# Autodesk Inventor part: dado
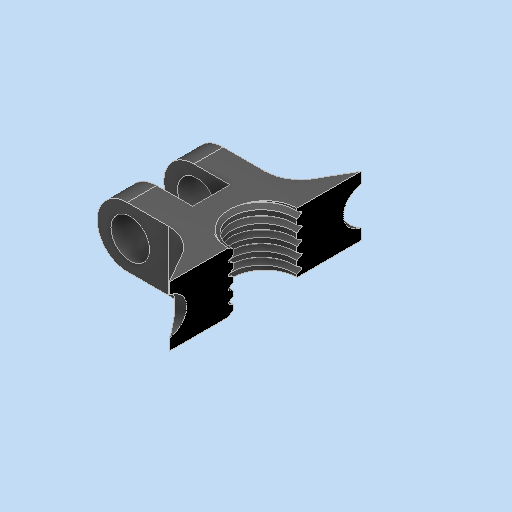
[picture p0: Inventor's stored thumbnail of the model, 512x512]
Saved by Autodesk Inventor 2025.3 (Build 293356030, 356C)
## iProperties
Created: 2026-05
Part Number: dado
Material: Generico
Document SubType Name: Modeling
Designer: R5800u
Density: 1 g/cm^3
Appearance: Default
Mass: 0.53278 g
Surface Area: 9.06232 cm^2
Volume: 0.53278 cm^3
Sending System: Autodesk Translation Framework v15.8.0.0
Preprocessor: ST-DEVELOPER v20.1
Title: dado.step
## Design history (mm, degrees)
feature "Corpo1"
sketch "Schizzo1"
  geometry: C1 r 2.65 at (7.5, -4); 1 further point
  constraints: 1 centre point, 1 coincident
  dimensions: "d0" = 5.3 diameter of C1
extrude "Estrusione1" cut sketch "Schizzo1" extent not by distance; stored distance "d1" = 0; taper "d2" = 0 deg
node "Solido1"
